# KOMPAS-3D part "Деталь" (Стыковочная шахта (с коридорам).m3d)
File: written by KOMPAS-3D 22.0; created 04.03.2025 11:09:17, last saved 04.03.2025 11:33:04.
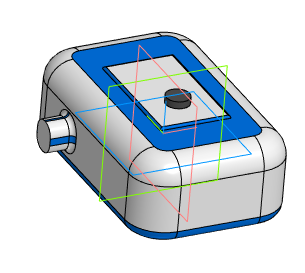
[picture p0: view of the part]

Document properties: Автор: Пользователь Windows; Полное имя файла: C:\Users\Student\Documents\Картошечка\База Сабнатика\Стыковочная шахта\Стыковочная шахта (с коридорам).m3d

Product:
- Body: Тело 1
    Масса: 1.418144
- Part/product: Деталь
    Масса: 1.441343

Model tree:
1. Эскиз:1
2. Элемент выдавливания:1
     Расстояние 1 = 35
3. Скругление:1  (with: Элемент выдавливания:1)
     Радиус = 15
4. Скругление:2  (with: Элемент выдавливания:1)
     Радиус = 10
5. Скругление:3  (with: Элемент выдавливания:1)
     Радиус = 5
6. Эскиз:2  (with: Элемент выдавливания:1)
7. Элемент выдавливания:2
     Расстояние 2 = 12
8. Эскиз:3  (with: Элемент выдавливания:1)
9. Элемент выдавливания:3
     Расстояние 1 = 1
10. Скругление:4  (with: Элемент выдавливания:3)
     Радиус = 1
11. Эскиз:4  (with: Элемент выдавливания:3)
12. Элемент выдавливания:4
     Расстояние 1 = 3
13. Эскиз:5  (with: Элемент выдавливания:1)
14. Элемент выдавливания:5
     Расстояние 1 = 10
15. Скругление:5  (with: Элемент выдавливания:5)
     Радиус = 2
